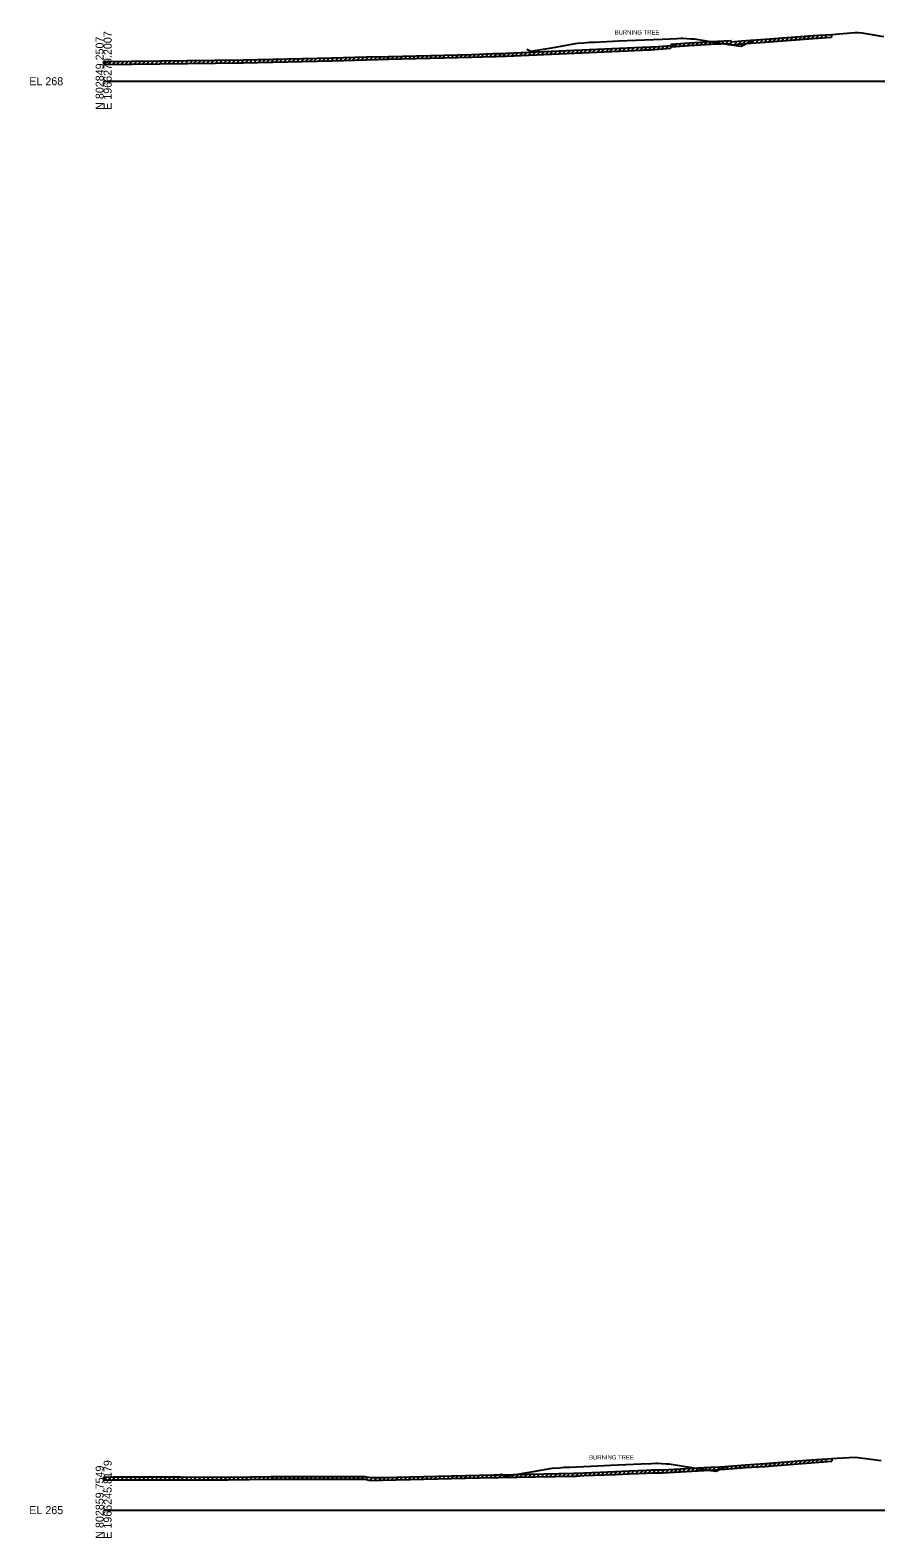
# Model space of a CAD drawing. Extents: x -26 to 1986619, y -10 to 827846.
# Drawn here: x -26 to 270, y 12990 to 13518 of the extents above; entities that cross this region are included whole.
import ezdxf

# ---------------------------------------------------------------- set-up
doc = ezdxf.new("R2010")
doc.units = 0
for name, color, linetype in [('Default', 7, 'Continuous'), ('RD_GPK_XS_Cell', 7, 'Continuous'), ('RD_TX_Misc1', 7, 'Continuous'), ('RD_XS_ExGround', 7, 'Continuous'), ('RD_XS_ExPaveRet', 7, 'Continuous'), ('RD_XS_Pave', 7, 'Continuous')]:
    doc.layers.add(name, color=color, linetype=linetype)

msp = doc.modelspace()

# ---------------------------------------------------------------- linework, layer by layer
at = {"layer": 'RD_GPK_XS_Cell'}
for p, q in [((0, 13500), (300, 13500)), ((0, 13000), (300, 13000))]:
    msp.add_line(p, q, dxfattribs=at)
at = {"layer": 'RD_XS_ExGround'}
for points in [[(0, 13506.87), (48.83, 13507.49), (79.87, 13508.16), (91.95, 13508.5), (99.68, 13508.69), (128.67, 13509.41), (136.25, 13509.66), (137.46, 13509.69), (139.23, 13509.74), (139.67, 13509.76), (140.76, 13509.81), (188.4, 13511.89), (189.9, 13511.96), (191.26, 13512.02), (194.06, 13512.18), (198.37, 13512.54), (198.53, 13513), (204.93, 13513.47), (212.35, 13513.95), (219.35, 13514.22), (219.45, 13513.78), (223.06, 13514.08), (231.32, 13514.72), (248.18, 13515.95), (254.55, 13516.41), (262.7, 13517.02), (263.97, 13517.1), (265.19, 13516.89), (272.71, 13515.61)], [(0, 13011.51), (3.46, 13011.62), (26.92, 13011.65), (43.48, 13011.57), (58.6, 13011.82), (91.38, 13011.79), (93.22, 13011.37), (96.73, 13011.44), (97.49, 13011.46), (136.22, 13012.39), (137.57, 13012.36), (138.04, 13012.37), (164.45, 13012.92), (165.33, 13012.94), (168.01, 13013.08), (179.04, 13013.5), (183.81, 13013.76), (186.95, 13013.86), (189.77, 13013.98), (191.76, 13014.1), (195.51, 13014.07), (212.1, 13015), (215.57, 13015.2), (217.24, 13015.33), (224.54, 13015.87), (231.24, 13016.3), (245.87, 13017.44), (254.64, 13018.1), (256.47, 13018.22), (263, 13018.59), (271.91, 13017.37)]]:
    msp.add_lwpolyline(points, dxfattribs=at)
at = {"layer": 'RD_XS_ExPaveRet'}
for p, q in [((252.1, 13515.23), (253.18, 13516.31)), ((254.55, 13516.41), (254.55, 13515.41)), ((166.6, 13509.94), (167.65, 13510.98)), ((168.1, 13510), (169.15, 13511.05)), ((169.6, 13510.07), (170.65, 13511.11)), ((171.1, 13510.13), (172.15, 13511.18)), ((172.6, 13510.2), (173.65, 13511.24)), ((174.1, 13510.26), (175.15, 13511.31)), ((175.6, 13510.33), (176.65, 13511.37)), ((177.1, 13510.39), (178.15, 13511.44)), ((178.6, 13510.46), (179.65, 13511.5)), ((180.1, 13510.52), (181.15, 13511.57)), ((181.6, 13510.59), (182.65, 13511.63)), ((183.1, 13510.65), (184.15, 13511.7)), ((184.6, 13510.72), (185.65, 13511.76)), ((186.1, 13510.78), (187.15, 13511.83)), ((187.6, 13510.85), (188.65, 13511.9)), ((188.4, 13510.89), (189.9, 13510.96)), ((189.1, 13510.92), (190.15, 13511.97)), ((189.9, 13510.96), (191.26, 13511.02)), ((190.6, 13510.99), (191.66, 13512.05)), ((191.26, 13511.02), (194.06, 13511.18)), ((192.1, 13511.07), (193.16, 13512.13)), ((193.6, 13511.16), (194.68, 13512.24)), ((194.06, 13511.18), (198.37, 13511.54)), ((195.1, 13511.27), (196.19, 13512.36)), ((196.6, 13511.4), (197.69, 13512.49)), ((198.1, 13511.52), (199.66, 13513.08)), ((198.37, 13511.54), (198.53, 13512)), ((198.53, 13512), (204.93, 13512.47)), ((199.6, 13512.08), (200.68, 13513.16)), ((201.1, 13512.19), (202.18, 13513.27)), ((202.6, 13512.3), (203.68, 13513.38)), ((204.1, 13512.41), (205.18, 13513.48)), ((204.93, 13512.47), (212.35, 13512.95)), ((205.6, 13512.51), (206.67, 13513.58)), ((207.1, 13512.61), (208.17, 13513.68)), ((208.6, 13512.7), (209.67, 13513.77)), ((210.1, 13512.8), (211.17, 13513.87)), ((211.6, 13512.9), (212.66, 13513.96)), ((212.35, 13512.95), (219.35, 13513.22)), ((213.1, 13512.98), (214.14, 13514.02)), ((214.6, 13513.04), (215.64, 13514.08)), ((216.1, 13513.1), (217.14, 13514.14)), ((217.6, 13513.15), (218.64, 13514.2)), ((219.1, 13513.21), (219.68, 13513.8)), ((219.35, 13513.22), (219.45, 13512.78)), ((219.45, 13512.78), (223.06, 13513.08)), ((220.6, 13512.87), (221.69, 13513.97)), ((222.1, 13513), (223.19, 13514.09)), ((223.06, 13513.08), (231.32, 13513.72)), ((223.6, 13513.13), (224.68, 13514.21)), ((225.1, 13513.24), (226.18, 13514.32)), ((226.6, 13513.36), (227.68, 13514.44)), ((228.1, 13513.47), (229.18, 13514.55)), ((229.6, 13513.58), (230.68, 13514.67)), ((231.1, 13513.7), (232.18, 13514.78)), ((231.32, 13513.72), (248.18, 13514.95)), ((232.6, 13513.81), (233.68, 13514.89)), ((234.1, 13513.92), (235.18, 13515)), ((235.6, 13514.03), (236.68, 13515.11)), ((237.1, 13514.14), (238.18, 13515.22)), ((238.6, 13514.25), (239.68, 13515.33)), ((240.1, 13514.36), (241.18, 13515.44)), ((241.6, 13514.47), (242.68, 13515.55)), ((243.1, 13514.58), (244.18, 13515.66)), ((244.6, 13514.69), (245.68, 13515.77)), ((246.1, 13514.8), (247.18, 13515.88)), ((247.6, 13514.91), (248.68, 13515.99)), ((248.18, 13514.95), (254.55, 13515.41)), ((249.1, 13515.02), (250.18, 13516.09)), ((250.6, 13515.12), (251.68, 13516.2)), ((0.1, 13505.88), (1.11, 13506.89)), ((0.1, 13505.88), (0.1, 13506.88)), ((0.1, 13505.88), (48.83, 13506.49)), ((1.6, 13505.89), (2.61, 13506.91)), ((3.1, 13505.91), (4.11, 13506.93)), ((4.6, 13505.93), (5.61, 13506.95)), ((6.1, 13505.95), (7.11, 13506.96)), ((7.6, 13505.97), (8.61, 13506.98)), ((9.1, 13505.99), (10.11, 13507)), ((10.6, 13506.01), (11.61, 13507.02)), ((12.1, 13506.03), (13.11, 13507.04)), ((13.6, 13506.05), (14.61, 13507.06)), ((15.1, 13506.07), (16.11, 13507.08)), ((16.6, 13506.09), (17.61, 13507.1)), ((18.1, 13506.1), (19.11, 13507.12)), ((19.6, 13506.12), (20.61, 13507.14)), ((21.1, 13506.14), (22.11, 13507.15)), ((22.6, 13506.16), (23.61, 13507.17)), ((24.1, 13506.18), (25.11, 13507.19)), ((25.6, 13506.2), (26.61, 13507.21)), ((27.1, 13506.22), (28.11, 13507.23)), ((28.6, 13506.24), (29.61, 13507.25)), ((30.1, 13506.26), (31.11, 13507.27)), ((31.6, 13506.28), (32.61, 13507.29)), ((33.1, 13506.29), (34.11, 13507.31)), ((34.6, 13506.31), (35.61, 13507.33)), ((36.1, 13506.33), (37.11, 13507.35)), ((37.6, 13506.35), (38.61, 13507.36)), ((39.1, 13506.37), (40.11, 13507.38)), ((40.6, 13506.39), (41.61, 13507.4)), ((42.1, 13506.41), (43.11, 13507.42)), ((43.6, 13506.43), (44.61, 13507.44)), ((45.1, 13506.45), (46.11, 13507.46)), ((46.6, 13506.47), (47.61, 13507.48)), ((48.1, 13506.48), (49.12, 13507.5)), ((48.83, 13506.49), (79.87, 13507.16)), ((49.6, 13506.51), (50.62, 13507.53)), ((51.1, 13506.54), (52.12, 13507.56)), ((52.6, 13506.57), (53.62, 13507.6)), ((54.1, 13506.61), (55.12, 13507.63)), ((55.6, 13506.64), (56.62, 13507.66)), ((57.1, 13506.67), (58.12, 13507.69)), ((58.6, 13506.7), (59.62, 13507.72)), ((60.1, 13506.73), (61.12, 13507.76)), ((61.6, 13506.77), (62.62, 13507.79)), ((63.1, 13506.8), (64.12, 13507.82)), ((64.6, 13506.83), (65.62, 13507.85)), ((66.1, 13506.86), (67.12, 13507.89)), ((67.6, 13506.9), (68.62, 13507.92)), ((69.1, 13506.93), (70.12, 13507.95)), ((70.6, 13506.96), (71.62, 13507.98)), ((72.1, 13506.99), (73.12, 13508.01)), ((73.6, 13507.02), (74.62, 13508.05)), ((75.1, 13507.06), (76.12, 13508.08)), ((76.6, 13507.09), (77.62, 13508.11)), ((78.1, 13507.12), (79.12, 13508.14)), ((79.6, 13507.15), (80.63, 13508.18)), ((79.87, 13507.16), (91.95, 13507.5)), ((81.1, 13507.19), (82.13, 13508.22)), ((82.6, 13507.23), (83.63, 13508.26)), ((84.1, 13507.28), (85.13, 13508.31)), ((85.6, 13507.32), (86.63, 13508.35)), ((87.1, 13507.36), (88.13, 13508.39)), ((88.6, 13507.4), (89.63, 13508.43)), ((90.1, 13507.44), (91.13, 13508.47)), ((91.6, 13507.49), (92.63, 13508.51)), ((91.95, 13507.5), (99.68, 13507.69)), ((93.1, 13507.52), (94.13, 13508.55)), ((94.6, 13507.56), (95.63, 13508.59)), ((96.1, 13507.6), (97.13, 13508.62)), ((97.6, 13507.64), (98.63, 13508.66)), ((99.1, 13507.67), (100.13, 13508.7)), ((99.68, 13507.69), (128.67, 13508.41)), ((100.6, 13507.71), (101.63, 13508.73)), ((102.1, 13507.75), (103.13, 13508.77)), ((103.6, 13507.78), (104.63, 13508.81)), ((105.1, 13507.82), (106.13, 13508.85)), ((106.6, 13507.86), (107.63, 13508.88)), ((108.1, 13507.9), (109.13, 13508.92)), ((109.6, 13507.93), (110.63, 13508.96)), ((111.1, 13507.97), (112.13, 13509)), ((112.6, 13508.01), (113.63, 13509.03)), ((114.1, 13508.04), (115.13, 13509.07)), ((115.6, 13508.08), (116.63, 13509.11)), ((117.1, 13508.12), (118.13, 13509.14)), ((118.6, 13508.16), (119.63, 13509.18)), ((120.1, 13508.19), (121.13, 13509.22)), ((121.6, 13508.23), (122.63, 13509.26)), ((123.1, 13508.27), (124.13, 13509.29)), ((124.6, 13508.31), (125.63, 13509.33)), ((126.1, 13508.34), (127.13, 13509.37)), ((127.6, 13508.38), (128.63, 13509.41)), ((128.67, 13508.41), (136.25, 13508.66)), ((129.1, 13508.42), (130.13, 13509.45)), ((130.6, 13508.47), (131.63, 13509.5)), ((132.1, 13508.52), (133.13, 13509.55)), ((133.6, 13508.57), (134.63, 13509.6)), ((135.1, 13508.62), (136.13, 13509.65)), ((136.25, 13508.66), (137.46, 13508.69)), ((136.6, 13508.66), (137.63, 13509.69)), ((137.46, 13508.69), (139.23, 13508.74)), ((138.1, 13508.71), (139.13, 13509.73)), ((139.23, 13508.74), (139.67, 13508.76)), ((139.6, 13508.75), (140.65, 13509.8)), ((139.67, 13508.76), (140.76, 13508.81)), ((140.76, 13508.81), (188.4, 13510.89)), ((141.1, 13508.83), (142.15, 13509.87)), ((142.6, 13508.89), (143.65, 13509.94)), ((144.1, 13508.96), (145.15, 13510)), ((145.6, 13509.02), (146.65, 13510.07)), ((147.1, 13509.09), (148.15, 13510.13)), ((148.6, 13509.15), (149.65, 13510.2)), ((150.1, 13509.22), (151.15, 13510.26)), ((151.6, 13509.28), (152.65, 13510.33)), ((153.1, 13509.35), (154.15, 13510.39)), ((154.6, 13509.41), (155.65, 13510.46)), ((156.1, 13509.48), (157.15, 13510.52)), ((157.6, 13509.54), (158.65, 13510.59)), ((159.1, 13509.61), (160.15, 13510.65)), ((160.6, 13509.67), (161.65, 13510.72)), ((162.1, 13509.74), (163.15, 13510.79)), ((163.6, 13509.8), (164.65, 13510.85)), ((165.1, 13509.87), (166.15, 13510.92)), ((213.1, 13014.06), (214.16, 13015.12)), ((214.6, 13014.15), (215.66, 13015.21)), ((216.1, 13014.24), (217.18, 13015.33)), ((217.6, 13014.36), (218.68, 13015.44)), ((219.1, 13014.47), (220.18, 13015.55)), ((220.6, 13014.58), (221.68, 13015.66)), ((222.1, 13014.69), (223.18, 13015.77)), ((223.6, 13014.8), (224.68, 13015.87)), ((224.54, 13014.87), (231.24, 13015.3)), ((225.1, 13014.9), (226.17, 13015.97)), ((226.6, 13015), (227.67, 13016.07)), ((228.1, 13015.09), (229.17, 13016.16)), ((229.6, 13015.19), (230.67, 13016.26)), ((231.1, 13015.29), (232.18, 13016.37)), ((231.24, 13015.3), (245.87, 13016.44)), ((232.6, 13015.4), (233.68, 13016.49)), ((234.1, 13015.52), (235.18, 13016.6)), ((235.6, 13015.64), (236.68, 13016.72)), ((237.1, 13015.75), (238.18, 13016.84)), ((238.6, 13015.87), (239.68, 13016.96)), ((240.1, 13015.99), (241.18, 13017.07)), ((241.6, 13016.11), (242.68, 13017.19)), ((243.1, 13016.22), (244.18, 13017.31)), ((244.6, 13016.34), (245.68, 13017.42)), ((245.87, 13016.44), (254.64, 13017.1)), ((246.1, 13016.46), (247.18, 13017.54)), ((247.6, 13016.57), (248.68, 13017.65)), ((249.1, 13016.68), (250.18, 13017.76)), ((250.6, 13016.79), (251.68, 13017.88)), ((252.1, 13016.91), (253.18, 13017.99)), ((254.64, 13018.1), (254.64, 13017.1)), ((0.1, 13010.52), (1.13, 13011.55)), ((0.1, 13010.52), (0.1, 13011.52)), ((0.1, 13010.52), (3.46, 13010.62)), ((1.6, 13010.56), (2.63, 13011.6)), ((3.1, 13010.61), (4.11, 13011.62)), ((3.46, 13010.62), (26.92, 13010.65)), ((4.6, 13010.62), (5.6, 13011.62)), ((6.1, 13010.62), (7.1, 13011.63)), ((7.6, 13010.63), (8.6, 13011.63)), ((9.1, 13010.63), (10.1, 13011.63)), ((10.6, 13010.63), (11.6, 13011.63)), ((12.1, 13010.63), (13.1, 13011.63)), ((13.6, 13010.63), (14.6, 13011.63)), ((15.1, 13010.63), (16.1, 13011.64)), ((16.6, 13010.64), (17.6, 13011.64)), ((18.1, 13010.64), (19.1, 13011.64)), ((19.6, 13010.64), (20.6, 13011.64)), ((21.1, 13010.64), (22.1, 13011.64)), ((22.6, 13010.64), (23.6, 13011.64)), ((24.1, 13010.65), (25.1, 13011.65)), ((25.6, 13010.65), (26.6, 13011.65)), ((26.92, 13010.65), (43.48, 13010.57)), ((27.1, 13010.65), (28.1, 13011.64)), ((28.6, 13010.64), (29.6, 13011.64)), ((30.1, 13010.63), (31.1, 13011.63)), ((31.6, 13010.63), (32.6, 13011.62)), ((33.1, 13010.62), (34.1, 13011.62)), ((34.6, 13010.61), (35.6, 13011.61)), ((36.1, 13010.61), (37.1, 13011.6)), ((37.6, 13010.6), (38.6, 13011.59)), ((39.1, 13010.59), (40.1, 13011.59)), ((40.6, 13010.59), (41.6, 13011.58)), ((42.1, 13010.58), (43.1, 13011.57)), ((43.48, 13010.57), (58.6, 13010.82)), ((43.6, 13010.57), (44.62, 13011.59)), ((45.1, 13010.6), (46.12, 13011.62)), ((46.6, 13010.62), (47.62, 13011.64)), ((48.1, 13010.65), (49.12, 13011.66)), ((49.6, 13010.67), (50.62, 13011.69)), ((51.1, 13010.7), (52.12, 13011.71)), ((52.6, 13010.72), (53.62, 13011.74)), ((54.1, 13010.75), (55.12, 13011.76)), ((55.6, 13010.77), (56.62, 13011.79)), ((57.1, 13010.79), (58.12, 13011.81)), ((58.6, 13010.82), (59.6, 13011.82)), ((58.6, 13010.82), (91.38, 13010.79)), ((60.1, 13010.82), (61.1, 13011.82)), ((61.6, 13010.82), (62.6, 13011.81)), ((63.1, 13010.81), (64.1, 13011.81)), ((64.6, 13010.81), (65.6, 13011.81)), ((66.1, 13010.81), (67.1, 13011.81)), ((67.6, 13010.81), (68.6, 13011.81)), ((69.1, 13010.81), (70.1, 13011.81)), ((70.6, 13010.81), (71.6, 13011.81)), ((72.1, 13010.81), (73.1, 13011.81)), ((73.6, 13010.81), (74.6, 13011.8)), ((75.1, 13010.8), (76.1, 13011.8)), ((76.6, 13010.8), (77.6, 13011.8)), ((78.1, 13010.8), (79.1, 13011.8)), ((79.6, 13010.8), (80.6, 13011.8)), ((81.1, 13010.8), (82.1, 13011.8)), ((82.6, 13010.8), (83.6, 13011.8)), ((84.1, 13010.8), (85.1, 13011.79)), ((85.6, 13010.79), (86.6, 13011.79)), ((87.1, 13010.79), (88.1, 13011.79)), ((88.6, 13010.79), (89.6, 13011.79)), ((90.1, 13010.79), (91.1, 13011.79)), ((91.38, 13010.79), (93.22, 13010.37)), ((91.6, 13010.74), (92.42, 13011.55)), ((93.1, 13010.4), (94.09, 13011.39)), ((93.22, 13010.37), (96.73, 13010.44)), ((94.6, 13010.4), (95.62, 13011.42)), ((96.1, 13010.43), (97.12, 13011.45)), ((96.73, 13010.44), (97.49, 13010.46)), ((97.49, 13010.46), (136.22, 13011.39)), ((97.6, 13010.46), (98.62, 13011.48)), ((99.1, 13010.49), (100.12, 13011.52)), ((100.6, 13010.53), (101.62, 13011.56)), ((102.1, 13010.57), (103.12, 13011.59)), ((103.6, 13010.6), (104.62, 13011.63)), ((105.1, 13010.64), (106.12, 13011.66)), ((106.6, 13010.67), (107.62, 13011.7)), ((108.1, 13010.71), (109.12, 13011.74)), ((109.6, 13010.75), (110.62, 13011.77)), ((111.1, 13010.78), (112.12, 13011.81)), ((112.6, 13010.82), (113.62, 13011.84)), ((114.1, 13010.85), (115.12, 13011.88)), ((115.6, 13010.89), (116.62, 13011.92)), ((117.1, 13010.93), (118.12, 13011.95)), ((118.6, 13010.96), (119.62, 13011.99)), ((120.1, 13011), (121.12, 13012.02)), ((121.6, 13011.04), (122.62, 13012.06)), ((123.1, 13011.07), (124.12, 13012.1)), ((124.6, 13011.11), (125.62, 13012.13)), ((126.1, 13011.14), (127.12, 13012.17)), ((127.6, 13011.18), (128.62, 13012.2)), ((129.1, 13011.22), (130.12, 13012.24)), ((130.6, 13011.25), (131.62, 13012.28)), ((132.1, 13011.29), (133.12, 13012.31)), ((133.6, 13011.32), (134.62, 13012.35)), ((135.1, 13011.36), (136.12, 13012.38)), ((136.22, 13011.39), (137.57, 13011.36)), ((136.6, 13011.38), (137.59, 13012.37)), ((137.57, 13011.36), (138.04, 13011.37)), ((138.04, 13011.37), (164.45, 13011.92)), ((138.1, 13011.38), (139.12, 13012.4)), ((139.6, 13011.41), (140.62, 13012.43)), ((141.1, 13011.44), (142.12, 13012.46)), ((142.6, 13011.47), (143.62, 13012.49)), ((144.1, 13011.5), (145.12, 13012.52)), ((145.6, 13011.53), (146.62, 13012.55)), ((147.1, 13011.56), (148.12, 13012.58)), ((148.6, 13011.59), (149.62, 13012.61)), ((150.1, 13011.62), (151.12, 13012.65)), ((151.6, 13011.66), (152.62, 13012.68)), ((153.1, 13011.69), (154.12, 13012.71)), ((154.6, 13011.72), (155.62, 13012.74)), ((156.1, 13011.75), (157.12, 13012.77)), ((157.6, 13011.78), (158.62, 13012.8)), ((159.1, 13011.81), (160.12, 13012.83)), ((160.6, 13011.84), (161.62, 13012.86)), ((162.1, 13011.87), (163.12, 13012.9)), ((163.6, 13011.91), (164.62, 13012.93)), ((164.45, 13011.92), (165.33, 13011.94)), ((165.1, 13011.94), (166.15, 13012.98)), ((165.33, 13011.94), (168.01, 13012.08)), ((166.6, 13012.01), (167.65, 13013.06)), ((168.01, 13012.08), (179.04, 13012.5)), ((168.1, 13012.08), (169.14, 13013.12)), ((169.6, 13012.14), (170.64, 13013.18)), ((171.1, 13012.2), (172.14, 13013.24)), ((172.6, 13012.25), (173.64, 13013.29)), ((174.1, 13012.31), (175.14, 13013.35)), ((175.6, 13012.37), (176.64, 13013.41)), ((177.1, 13012.42), (178.14, 13013.46)), ((178.6, 13012.48), (179.65, 13013.53)), ((179.04, 13012.5), (183.81, 13012.76)), ((180.1, 13012.56), (181.16, 13013.62)), ((181.6, 13012.64), (182.66, 13013.7)), ((183.1, 13012.72), (184.15, 13013.77)), ((183.81, 13012.76), (186.95, 13012.86)), ((184.6, 13012.79), (185.63, 13013.82)), ((186.1, 13012.83), (187.13, 13013.86)), ((186.95, 13012.86), (189.77, 13012.98)), ((187.6, 13012.89), (188.65, 13013.93)), ((189.1, 13012.95), (190.15, 13014.01)), ((189.77, 13012.98), (191.76, 13013.1)), ((190.6, 13013.03), (191.66, 13014.1)), ((191.76, 13013.1), (195.51, 13013.07)), ((192.1, 13013.1), (193.09, 13014.09)), ((193.6, 13013.09), (194.59, 13014.08)), ((195.1, 13013.08), (196.13, 13014.11)), ((195.51, 13013.07), (212.1, 13014)), ((196.6, 13013.13), (197.66, 13014.19)), ((198.1, 13013.22), (199.16, 13014.28)), ((199.6, 13013.3), (200.66, 13014.36)), ((201.1, 13013.39), (202.16, 13014.44)), ((202.6, 13013.47), (203.66, 13014.53)), ((204.1, 13013.55), (205.16, 13014.61)), ((205.6, 13013.64), (206.66, 13014.7)), ((207.1, 13013.72), (208.16, 13014.78)), ((208.6, 13013.81), (209.66, 13014.86)), ((210.1, 13013.89), (211.16, 13014.95)), ((211.6, 13013.97), (212.66, 13015.03)), ((212.1, 13014), (215.57, 13014.2)), ((215.57, 13014.2), (217.24, 13014.33)), ((217.24, 13014.33), (224.54, 13014.87))]:
    msp.add_line(p, q, dxfattribs=at)
at = {"layer": 'RD_XS_Pave'}
for points in [[(147.98, 13511.17), (149.43, 13510.48), (157.38, 13511.83), (165.77, 13513.27), (167.96, 13513.45), (169.86, 13513.62), (170.98, 13513.67), (171.9, 13513.71), (180.23, 13514.08), (186.2, 13514.35), (195.41, 13514.75), (200.51, 13514.98), (201.88, 13515.04), (202.55, 13515.07), (205.35, 13514.87), (206.64, 13514.78), (218.61, 13512.9), (222.98, 13512.22), (223.91, 13512.68), (227.54, 13514.49)], [(138.73, 13012.71), (140.53, 13011.85), (150.29, 13013.51), (156.88, 13014.64), (159.48, 13014.86), (160.96, 13014.99), (162.29, 13015.05), (163.01, 13015.08), (172.87, 13015.52), (177.31, 13015.72), (188.03, 13016.19), (191.62, 13016.35), (193.19, 13016.42), (193.66, 13016.44), (196.87, 13016.21), (197.75, 13016.15), (211.45, 13014.01), (214.1, 13013.6), (214.44, 13013.77), (217.68, 13015.38)]]:
    msp.add_lwpolyline(points, dxfattribs=at)

# ---------------------------------------------------------------- texts
at = {"layer": 'Default'}
for p in [(0, 13500), (0, 13000)]:
    msp.add_text('-', height=0.0001, dxfattribs=at).set_placement(p)
at = {"layer": 'RD_GPK_XS_Cell'}
for s, p in [('E 1966279.2007', (2.8, 13490)), ('N 802849.2507', (0, 13490)), ('N 802859.7549', (0, 12990)), ('E 1966245.8179', (2.8, 12990))]:
    msp.add_text(s, height=2.8, rotation=90, dxfattribs=at).set_placement(p)
for s, p in [('EL 268', (-26, 13498.6)), ('EL 265', (-26, 12998.6))]:
    msp.add_text(s, height=2.8, dxfattribs=at).set_placement(p)
at = {"layer": 'RD_TX_Misc1'}
for p in [(178.73, 13516.35), (169.79, 13017.73)]:
    msp.add_text('BURNING TREE', height=1.5, dxfattribs=at).set_placement(p)

doc.saveas('drawing.dxf')
